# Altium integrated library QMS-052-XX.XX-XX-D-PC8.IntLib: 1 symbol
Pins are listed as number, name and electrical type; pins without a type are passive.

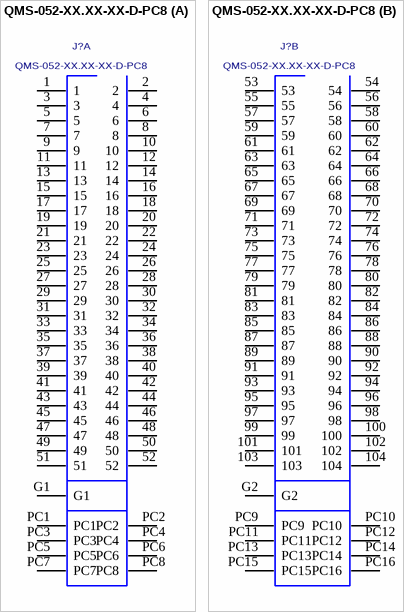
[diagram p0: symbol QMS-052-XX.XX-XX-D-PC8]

## QMS-052-XX.XX-XX-D-PC8
designator J?
HIGH SPEED SHIELDED TERMINAL, .025" (.635mm) PITCH; MANUFACTURER: SAMTEC
footprint QMS-052-XX.XX-XX-D-PC8
part A pins: 1, 2, 3, 4, 5, 6, 7, 8, 9, 10, 11, 12, 13, 14, 15, 16, 17, 18, 19, 20, 21, 22, 23, 24, 25, 26, 27, 28, 29, 30, 31, 32, 33, 34, 35, 36, 37, 38, 39, 40, 41, 42, 43, 44, 45, 46, 47, 48, 49, 50, 51, 52, G1, PC1, PC2, PC3, PC4, PC5, PC6, PC7, PC8
part B pins: 53, 54, 55, 56, 57, 58, 59, 60, 61, 62, 63, 64, 65, 66, 67, 68, 69, 70, 71, 72, 73, 74, 75, 76, 77, 78, 79, 80, 81, 82, 83, 84, 85, 86, 87, 88, 89, 90, 91, 92, 93, 94, 95, 96, 97, 98, 99, 100, 101, 102, 103, 104, G2, PC9, PC10, PC11, PC12, PC13, PC14, PC15, PC16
